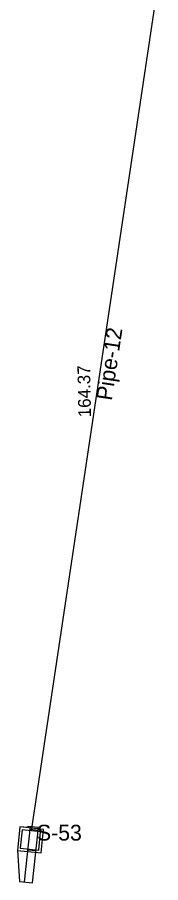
# Model space of a CAD drawing. Extents: x 925371 to 925937, y 853654 to 858024.
# Drawn here: x 925756.6 to 925783.7, y 857586.2 to 857749.9 of the extents above; entities that cross this region are included whole.
import ezdxf

# ---------------------------------------------------------------- set-up
doc = ezdxf.new("R2010")
doc.units = 0
for name, color, linetype in [('GPKDrBack_dp', 7, 'Continuous'), ('GPKDrBottom_dp', 7, 'Continuous'), ('GPKDrCellIns_dp', 7, 'Continuous'), ('GPKDrCentroid_dp', 7, 'Continuous'), ('GPKDrFront_dp', 7, 'Continuous'), ('GPKDrPipe_dp', 7, 'Continuous'), ('GPKDrPipeCir_dp', 7, 'Continuous'), ('InletBottomP', 7, 'Continuous'), ('InletCurb', 7, 'Continuous'), ('NonPlottingEle_dp', 7, 'Continuous'), ('PipeCulvert', 7, 'Continuous')]:
    doc.layers.add(name, color=color, linetype=linetype)

msp = doc.modelspace()

# ---------------------------------------------------------------- linework, layer by layer
at = {"layer": 'GPKDrBack_dp'}
for p, q in [((925756.88, 857594.56), (925756.88, 857594.56)), ((925757.38, 857594.5), (925757.38, 857594.5))]:
    msp.add_line(p, q, dxfattribs=at)
at = {"layer": 'GPKDrBottom_dp'}
for p, q in [((925757.56, 857596.24), (925757.56, 857596.24)), ((925757.56, 857596.24), (925757.56, 857596.24)), ((925759.3, 857596.06), (925759.3, 857596.06)), ((925759.3, 857596.06), (925759.3, 857596.06)), ((925761.04, 857595.88), (925761.04, 857595.88)), ((925761.04, 857595.88), (925761.04, 857595.88)), ((925757.38, 857594.5), (925757.38, 857594.5)), ((925757.38, 857594.5), (925757.38, 857594.5)), ((925759.12, 857594.32), (925759.12, 857594.32)), ((925759.12, 857594.32), (925759.12, 857594.32)), ((925757.2, 857592.76), (925757.2, 857592.76)), ((925757.2, 857592.76), (925757.2, 857592.76)), ((925758.94, 857592.58), (925758.94, 857592.58)), ((925758.94, 857592.58), (925758.94, 857592.58)), ((925760.86, 857594.14), (925760.86, 857594.14)), ((925760.86, 857594.14), (925760.86, 857594.14)), ((925760.68, 857592.4), (925760.68, 857592.4)), ((925760.68, 857592.4), (925760.68, 857592.4))]:
    msp.add_line(p, q, dxfattribs=at)
at = {"layer": 'GPKDrCellIns_dp'}
for p, q in [((925759.12, 857594.32), (925759.12, 857594.32)), ((925760.36, 857594.19), (925760.36, 857594.19))]:
    msp.add_line(p, q, dxfattribs=at)
at = {"layer": 'GPKDrCentroid_dp'}
msp.add_line((925759.12, 857594.32), (925759.12, 857594.32), dxfattribs=at)
at = {"layer": 'GPKDrFront_dp'}
for p, q in [((925760.36, 857594.19), (925760.36, 857594.19)), ((925760.86, 857594.14), (925760.86, 857594.14))]:
    msp.add_line(p, q, dxfattribs=at)
at = {"layer": 'GPKDrPipe_dp'}
for p, q in [((925759.3, 857596.06), (925759.3, 857596.06)), ((925759.3, 857596.06), (925759.3, 857596.06)), ((925757.38, 857594.5), (925757.38, 857594.5)), ((925757.38, 857594.5), (925757.38, 857594.5)), ((925758.94, 857592.58), (925758.94, 857592.58)), ((925758.94, 857592.58), (925758.94, 857592.58)), ((925760.86, 857594.14), (925760.86, 857594.14)), ((925760.86, 857594.14), (925760.86, 857594.14))]:
    msp.add_line(p, q, dxfattribs=at)
at = {"layer": 'GPKDrPipeCir_dp'}
msp.add_lwpolyline([(925760.68, 857592.4), (925761.04, 857595.88), (925757.56, 857596.24), (925757.2, 857592.76)], close=True, dxfattribs=at)
at = {"layer": 'InletBottomP'}
for points in [[(925757.12, 857596.79), (925756.65, 857592.32), (925761.12, 857591.85), (925761.59, 857596.32)], [(925761.04, 857595.88), (925757.56, 857596.24), (925757.2, 857592.76), (925760.68, 857592.4)]]:
    msp.add_lwpolyline(points, close=True, dxfattribs=at)
at = {"layer": 'InletCurb'}
for p, q in [((925757.12, 857596.79), (925756.65, 857592.32)), ((925758.61, 857596.64), (925757.12, 857596.79)), ((925758.03, 857586.39), (925759.13, 857596.83)), ((925758.63, 857596.88), (925758.61, 857596.64)), ((925760.62, 857596.68), (925758.63, 857596.88)), ((925760.57, 857596.13), (925759.07, 857596.28)), ((925759.53, 857586.23), (925760.62, 857596.68)), ((925756.65, 857592.32), (925757.04, 857586.49)), ((925760.16, 857592.24), (925758.67, 857592.4)), ((925757.04, 857586.49), (925759.53, 857586.23))]:
    msp.add_line(p, q, dxfattribs=at)
at = {"layer": 'PipeCulvert'}
msp.add_line((925759.3, 857596.06), (925783.73, 857759.38), dxfattribs=at)

# ---------------------------------------------------------------- texts
at = {"layer": 'NonPlottingEle_dp'}
for s, height, rotation, p in [('Pipe-12', 3, 81.4942, (925774.48, 857677.28)), ('164.37', 2.4, 90.9741, (925770.56, 857674.25))]:
    msp.add_text(s, height=height, rotation=rotation, dxfattribs=at).set_placement(p)
msp.add_text('S-53', height=3, dxfattribs=at).set_placement((925760.36, 857594.19))

doc.saveas('drawing.dxf')
